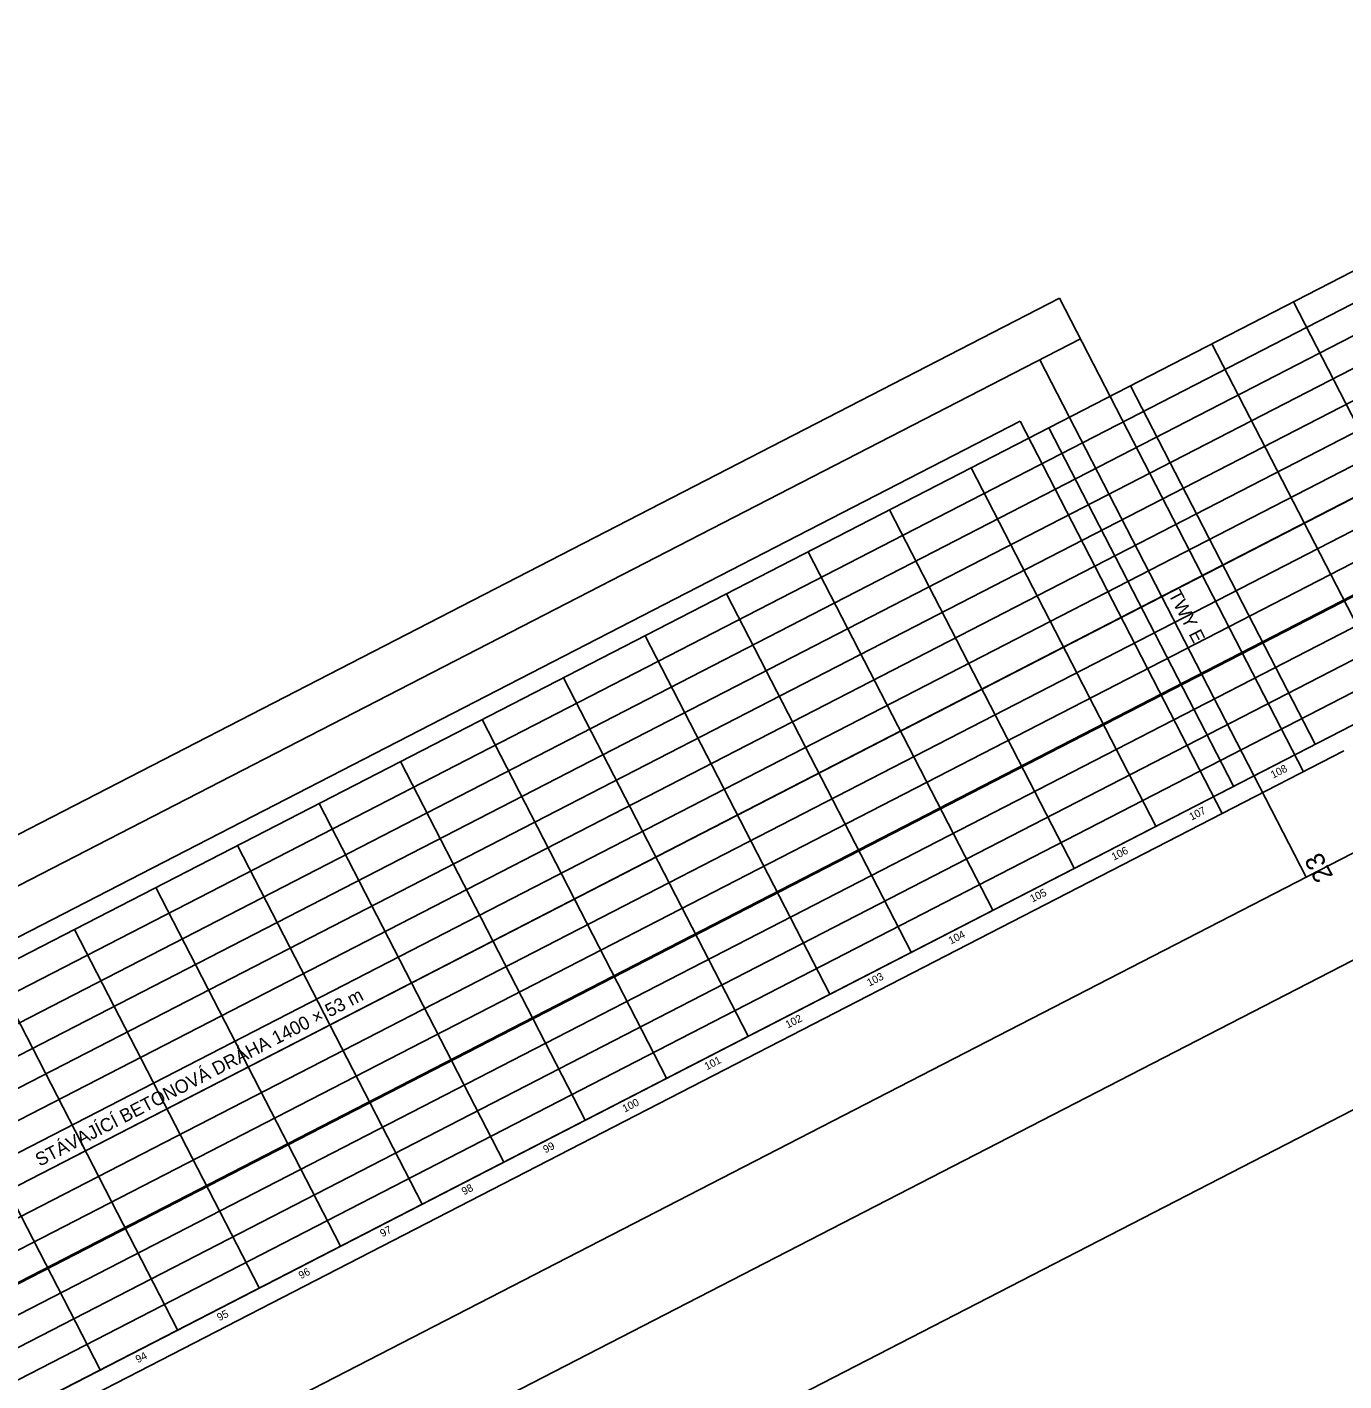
# Model space of a CAD drawing. Extents: x -886320 to -884760, y -1024172 to -1023483.
# Drawn here: x -885021.6 to -884848.5, y -1023661.3 to -1023483.3 of the extents above; entities that cross this region are included whole.
import ezdxf

# ---------------------------------------------------------------- set-up
doc = ezdxf.new("R2010")
doc.units = 0
for name, color, linetype in [('AGA__Netisknout', 7, 'Continuous'), ('Stavajici_betonova_draha', 7, 'Continuous'), ('Stavajici_betonova_draha_osa', 7, 'Continuous'), ('Stavajici_betonova_draha_popis', 7, 'Continuous'), ('Stavajici_betonova_draha_Popis desky', 7, 'Continuous'), ('Stavajici_betonova_draha_Spára', 7, 'Continuous'), ('Stavajici_drahovy_system', 7, 'Continuous'), ('Stavajici_drahovy_system_osy', 7, 'Continuous'), ('Stavajici_drahovy_system_popis', 7, 'Continuous'), ('Stavajici_drahovy_system_RWY_strip', 7, 'Continuous'), ('Stavajici_drahovy_system_TWY', 7, 'Continuous'), ('Stavajici_drahovy_system_TWY_osy', 7, 'Continuous'), ('Stavajici_drahovy_system_TWY_popis', 7, 'Continuous')]:
    doc.layers.add(name, color=color, linetype=linetype)

msp = doc.modelspace()

# ---------------------------------------------------------------- linework, layer by layer
at = {"layer": 'AGA__Netisknout'}
msp.add_line((-886017.78, -1024147.99), (-884773.13, -1023507.02), dxfattribs=at)
at = {"layer": 'Stavajici_betonova_draha'}
for p, q in [((-886029.69, -1024124.32), (-884785.04, -1023483.35)), ((-886029.69, -1024124.32), (-884785.04, -1023483.35)), ((-886005.42, -1024171.44), (-884760.77, -1023530.47)), ((-886005.42, -1024171.44), (-884760.77, -1023530.47))]:
    msp.add_line(p, q, dxfattribs=at)
at = {"layer": 'Stavajici_betonova_draha_osa'}
msp.add_line((-886017.55, -1024147.88), (-884772.9, -1023506.91), dxfattribs=at)
at = {"layer": 'Stavajici_betonova_draha_Spára'}
for p, q in [((-886029.91, -1024124.43), (-884785.26, -1023483.46)), ((-886028.18, -1024127.8), (-884783.53, -1023486.82)), ((-886026.44, -1024131.16), (-884781.79, -1023490.19)), ((-886024.71, -1024134.53), (-884780.06, -1023493.56)), ((-886022.98, -1024137.89), (-884778.33, -1023496.92)), ((-886021.24, -1024141.26), (-884776.59, -1023500.29)), ((-886019.51, -1024144.63), (-884774.86, -1023503.65)), ((-886016.04, -1024151.36), (-884771.39, -1023510.39)), ((-886014.31, -1024154.72), (-884769.66, -1023513.75)), ((-886012.58, -1024158.09), (-884767.93, -1023517.12)), ((-884855.17, -1023519.46), (-884830.91, -1023566.59)), ((-886010.84, -1024161.46), (-884766.19, -1023520.48)), ((-886009.11, -1024164.82), (-884764.46, -1023523.85)), ((-884865.89, -1023524.98), (-884841.62, -1023572.1)), ((-886007.38, -1024168.19), (-884762.73, -1023527.21)), ((-886005.64, -1024171.55), (-884760.99, -1023530.58)), ((-884876.6, -1023530.5), (-884852.33, -1023577.62)), ((-884887.31, -1023536.01), (-884863.05, -1023583.14)), ((-884897.53, -1023541.27), (-884873.26, -1023588.4)), ((-884908.24, -1023546.79), (-884883.97, -1023593.91)), ((-884918.95, -1023552.31), (-884894.69, -1023599.43)), ((-884929.67, -1023557.82), (-884905.4, -1023604.95)), ((-884940.38, -1023563.34), (-884916.11, -1023610.46)), ((-884951.09, -1023568.86), (-884926.82, -1023615.98)), ((-884961.8, -1023574.38), (-884937.54, -1023621.5)), ((-884972.52, -1023579.89), (-884948.25, -1023627.02)), ((-884983.23, -1023585.41), (-884958.96, -1023632.53)), ((-884993.94, -1023590.93), (-884969.68, -1023638.05)), ((-885004.66, -1023596.44), (-884980.39, -1023643.57)), ((-885015.37, -1023601.96), (-884991.1, -1023649.08)), ((-885026.08, -1023607.48), (-885001.81, -1023654.6)), ((-885036.26, -1023612.72), (-885012, -1023659.84))]:
    msp.add_line(p, q, dxfattribs=at)
at = {"layer": 'Stavajici_drahovy_system'}
for p, q in [((-884864.53, -1023586.71), (-884848.53, -1023578.47)), ((-885721.56, -1024028.07), (-884864.53, -1023586.71)), ((-885726.12, -1024058.54), (-884837.08, -1023600.7)), ((-885744.78, -1024087.83), (-884802.4, -1023602.52))]:
    msp.add_line(p, q, dxfattribs=at)
at = {"layer": 'Stavajici_drahovy_system_osy'}
msp.add_line((-885731.84, -1024047.42), (-884842.81, -1023589.59), dxfattribs=at)
at = {"layer": 'Stavajici_drahovy_system_RWY_strip'}
for p, q in [((-885772.25, -1024034.49), (-884829.87, -1023549.18)), ((-884802.4, -1023602.52), (-885744.78, -1024087.83))]:
    msp.add_line(p, q, dxfattribs=at)
at = {"layer": 'Stavajici_drahovy_system_TWY'}
for p, q in [((-885887.27, -1024034.67), (-884885.91, -1023518.99)), ((-884853.86, -1023581.22), (-884885.91, -1023518.99)), ((-885748.12, -1023976.51), (-884891.09, -1023535.15)), ((-884864.53, -1023586.71), (-884891.09, -1023535.15))]:
    msp.add_line(p, q, dxfattribs=at)
at = {"layer": 'Stavajici_drahovy_system_TWY_osy'}
for p, q in [((-885886.7, -1024041.13), (-884883.17, -1023524.32)), ((-884853.47, -1023595.08), (-884888.5, -1023527.07))]:
    msp.add_line(p, q, dxfattribs=at)

# ---------------------------------------------------------------- texts
at = {"layer": 'Stavajici_betonova_draha_popis'}
msp.add_text('STÁVAJÍCÍ BETONOVÁ DRÁHA 1400 × 53 m', height=1.75, rotation=27.2477, dxfattribs=at).set_placement((-885019.95, -1023633.15))
at = {"layer": 'Stavajici_betonova_draha_Popis desky'}
for s, p in [('108', (-884857.84, -1023582.14)), ('107', (-884868.55, -1023587.66)), ('106', (-884878.76, -1023592.92)), ('105', (-884889.48, -1023598.44)), ('104', (-884900.19, -1023603.95)), ('103', (-884910.9, -1023609.47)), ('102', (-884921.61, -1023614.98)), ('101', (-884932.26, -1023620.47)), ('100', (-884943.04, -1023626.02)), ('99', (-884953.47, -1023631.39)), ('98', (-884964.18, -1023636.91)), ('97', (-884974.9, -1023642.42)), ('96', (-884985.61, -1023647.94)), ('95', (-884996.33, -1023653.46)), ('94', (-885007.03, -1023658.98))]:
    msp.add_text(s, height=1, rotation=27.2477, dxfattribs=at).set_placement(p)
at = {"layer": 'Stavajici_drahovy_system_popis'}
msp.add_text('23', height=2.5, rotation=117.2477, dxfattribs=at).set_placement((-884849.89, -1023594.95))
at = {"layer": 'Stavajici_drahovy_system_TWY_popis'}
msp.add_text('TWY E', height=1.75, rotation=297.2477, dxfattribs=at).set_placement((-884871.64, -1023557.9))

doc.saveas('drawing.dxf')
